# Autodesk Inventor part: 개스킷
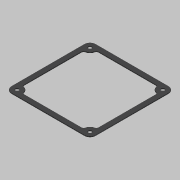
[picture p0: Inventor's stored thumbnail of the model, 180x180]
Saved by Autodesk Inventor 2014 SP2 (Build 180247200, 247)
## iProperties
Created: 2019-04
Part Number: 개스킷
Material: 고무
Document SubType Name: Modeling
Designer: mduedu
Density: 1 g/cm^3
Appearance: 고무 - 검은색 - 버전 1.1
Author: mduedu
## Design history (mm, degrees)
sketch "스케치1"
  geometry: L1 (52.5, 52.5)-(-52.5, 52.5); L2 (-52.5, 52.5)-(-52.5, -52.5); L3 (-52.5, -52.5)-(52.5, -52.5); L4 (52.5, -52.5)-(52.5, 52.5); L5 (52.5, 52.5)-(-52.5, -52.5); L6 (-52.5, 52.5)-(52.5, -52.5); 1 further point
  constraints: 12 end point, 2 midpoint, 2 parallel, 1 horizontal, 1 perpendicular
  dimensions: "d0" = 105 distance of L3.end L2.end; "d1" = 105 distance of L2.end L1.end
extrude "돌출1" new body sketch "스케치1" distance "d2" = 1; taper "d3" = 0 deg
sketch "스케치2"
  geometry: L1 (-52.5, -52.5)-(52.5, -52.5) reference; L2 (52.5, -52.5)-(52.5, 52.5) reference; L3 (52.5, 52.5)-(-52.5, 52.5) reference; L4 (-52.5, 52.5)-(-52.5, -52.5) reference; L5 (-46.5, 46.5)-(46.5, 46.5); L6 (46.5, 46.5)-(46.5, -46.5); L7 (46.5, -46.5)-(-46.5, -46.5); L8 (-46.5, -46.5)-(-46.5, 46.5); 1 further point
  constraints: 8 end point, 3 other
  dimensions: "d4" = 6 distance between parallel lines of L5 L3
extrude "돌출2" cut sketch "스케치2" stored distance "d5" = 1; taper "d6" = 0 deg
fillet "모깎기1" dims "d7" = 7
sketch "스케치3"
  geometry: A1 r 7 centre (-45.5, 45.5) between (-45.5, 52.5) and (-52.5, 45.5) reference; A2 r 7 centre (-45.5, -45.5) between (-52.5, -45.5) and (-45.5, -52.5) reference; A3 r 7 centre (45.5, -45.5) between (45.5, -52.5) and (52.5, -45.5) reference; A4 r 7 centre (45.5, 45.5) between (52.5, 45.5) and (45.5, 52.5) reference; 5 further points
  constraints: 4 coincident, 4 vertical alignment, 8 other
extrude "돌출3" join sketch "스케치3" stored distance "d8" = 1; taper "d9" = 0 deg
fillet "모깎기2" dims "d10" = 3
sketch "스케치4"
  geometry: A1 r 7 centre (-45.5, 45.5) between (-45.5, 52.5) and (-52.5, 45.5) reference; A2 r 7 centre (45.5, 45.5) between (52.5, 45.5) and (45.5, 52.5) reference; A3 r 7 centre (45.5, -45.5) between (45.5, -52.5) and (52.5, -45.5) reference; A4 r 7 centre (-45.5, -45.5) between (-52.5, -45.5) and (-45.5, -52.5) reference; 5 further points
  constraints: 4 coincident
hole "구멍1" sketch "스케치4" at (-45.5, 45.5), (45.5, 45.5), (45.5, -45.5), (-45.5, -45.5) diameter "d11" = 4.5; stored, may be unused: countersink angle "d15" = 90 deg, drill point angle "d17" = 118 deg; dims "d12" = 6, "d13" = 4, "d14" = 2, "d16" = 8
node "솔리드1"
node "투영된 루프1"
